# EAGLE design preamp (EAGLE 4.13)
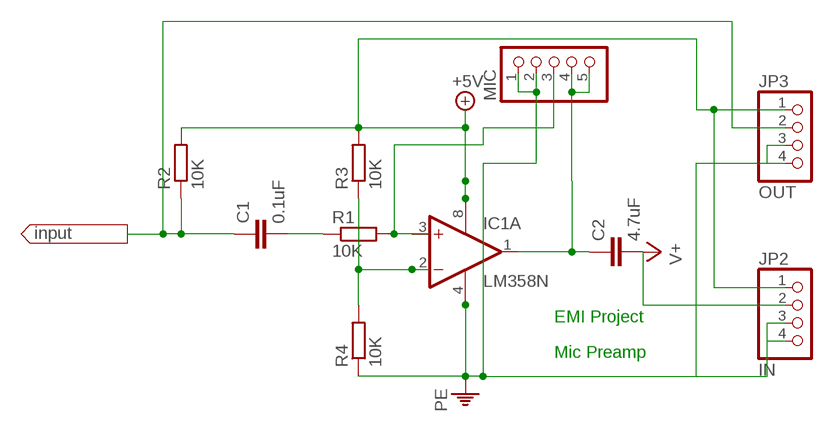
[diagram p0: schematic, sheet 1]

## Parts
C1  0.1uF  C-EU025-024X044  [C025-024X044]
C2  4.7uF  C-EU025-024X044  [C025-024X044]
IC1  LM358N  [DIL08]
JP2  IN  PINHD-1X4  [1X04]
JP3  OUT  PINHD-1X4  [1X04]
MIC  PINHD-1X5  [1X05]
R1  10K  R-EU_0207/7  [0207/7]
R2  10K  R-EU_0207/7  [0207/7]
R3  10K  R-EU_0207/7  [0207/7]
R4  10K  R-EU_0207/7  [0207/7]

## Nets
+9V: IC1.8(P:V+) JP2.1 JP3.1 R2.2 R3.2 ; supply symbol labelled +5V
N$1: C1.2 R1.1
N$2: C2.1 IC1.1(A:OUT) MIC.4 MIC.5
N$3: C1.1 JP3.2 R2.1
N$6: IC1.2(A:-IN) R3.1 R4.2
N$7: MIC.3 R1.2
PE: IC1.4(P:V-) JP2.3 JP2.4 JP3.3 JP3.4 MIC.1 MIC.2 R4.1
V+: C2.2 JP2.2
Unconnected: IC1.3(A:+IN) IC1.5(B:+IN) IC1.6(B:-IN) IC1.7(B:OUT)

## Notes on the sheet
- EMI Project
- Mic Preamp

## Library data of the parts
C1 C2 = rcl:C-EU: CAPACITOR, European symbol
IC1 = linear:LM358: OP AMP also LM158; LM258; LM2904 Source: http://cache.national.com/ds/LM/LM158.pdf
JP2 JP3 = pinhead:PINHD-1X4: PIN HEADER
MIC = pinhead:PINHD-1X5: PIN HEADER
R1-R4 = rcl:R-EU_: RESISTOR, European symbol

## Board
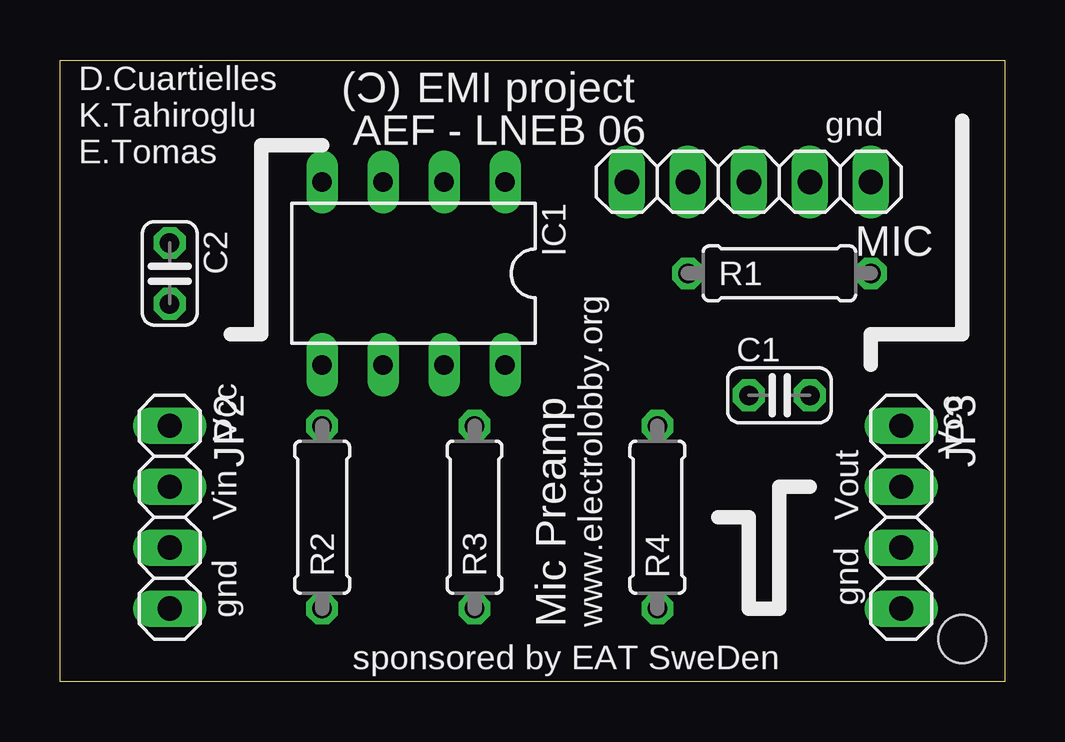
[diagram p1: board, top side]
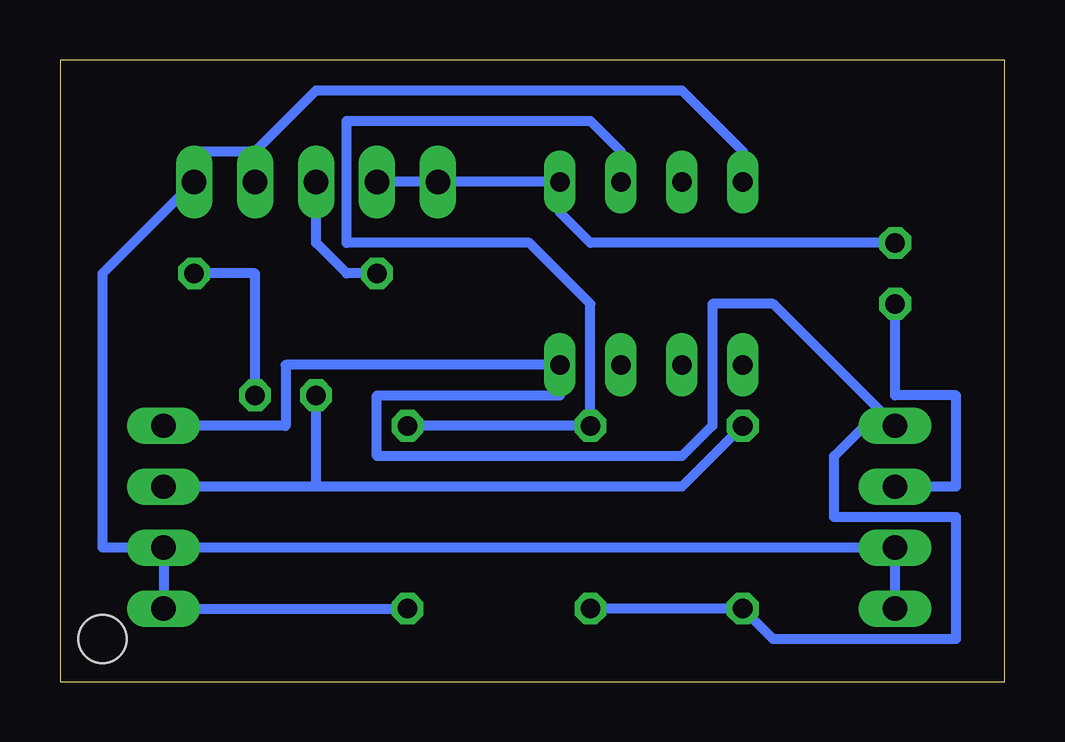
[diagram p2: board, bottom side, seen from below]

Size 39.37 x 25.91 mm. Coordinates in mm from the lower left corner, seen from the top.
Outline: 0,0 0,25.91 39.37,25.91 39.37,0 0,0
Copper layers (1*16): Top 0.035mm / dielectric 1.5mm / Bottom 0.035mm
Design rules "default": minimum track width 10mil, minimum drill 24mil, track to track 8mil, track to pad 8mil, pad to pad 8mil, via to via 8mil, smd to smd 8mil, copper to edge 40mil, drill to drill 8mil, minimum pad ring 10mil, minimum via ring 8mil, stop-mask expansion 4mil, vias tented up to drill 0mil, thermal gap 10mil
Holes 2 mm at 37.59,1.78

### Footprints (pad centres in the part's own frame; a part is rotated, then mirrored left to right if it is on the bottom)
C025-024X044 = drill 0.813 octagon: 1 -1.27,0; 2 1.27,0
DIL08 = drill 0.813 long: 1 -3.81,-3.81; 2 -1.27,-3.81; 3 1.27,-3.81; 4 3.81,-3.81; 5 3.81,3.81; 6 1.27,3.81; 7 -1.27,3.81; 8 -3.81,3.81
1X04 = drill 1.016 long: 1 -3.81,0; 2 -1.27,0; 3 1.27,0; 4 3.81,0
1X05 = drill 1.016 long: 1 -5.08,0; 2 -2.54,0; 3 0,0; 4 2.54,0; 5 5.08,0
0207/7 = drill 0.813 octagon: 1 -3.81,0; 2 3.81,0

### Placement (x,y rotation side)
C1  29.97,11.94 0 top
C2  4.57,17.02 270 top
IC1  14.73,17.02 180 top
JP2  4.57,6.86 270 top
JP3  35.05,6.86 270 top
MIC  28.7,20.83 180 top
R1  29.97,17.02 180 top
R2  10.92,6.86 270 top
R3  17.27,6.86 270 top
R4  24.89,6.86 90 top

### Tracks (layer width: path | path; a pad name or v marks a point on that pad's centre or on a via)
+9V
  Bottom 0.406: JP3.1 29.97,10.67 29.97,13.21 IC1.8 18.54,11.94 26.16,11.94 26.16,9.4 13.46,9.4 12.19,10.67 12.19,15.75 9.65,15.75 JP2.1 5.84,10.67 7.11,9.4 7.11,6.86 2.03,6.86 2.03,1.78 9.65,1.78 R2.2 R3.2
N$1
  Bottom 0.406: C1.2 31.24,17.02 R1.1
N$2
  Bottom 0.406: MIC.4 MIC.5 IC1.1 18.54,19.56 17.27,18.29 C2.1
N$3
  Bottom 0.406: R2.1 13.46,8.13 28.7,8.13 | 28.7,8.13 JP3.2 | 28.7,8.13 C1.1
N$6
  Bottom 0.406: R4.2 R3.1 17.27,15.75 19.81,18.29 27.43,18.29 27.43,23.37 17.27,23.37 16,22.1 IC1.2
N$7
  Bottom 0.406: R1.2 27.43,17.02 28.7,18.29 MIC.3
PE
  Bottom 0.406: 31.24,22.1 28.7,24.64 13.46,24.64 10.92,22.1 IC1.4 | 31.24,22.1 33.78,22.1 MIC.1 37.59,17.02 37.59,5.59 JP3.3 | 31.24,22.1 MIC.2 | JP2.4 JP2.3 JP3.3 | R4.1 JP3.4 JP3.3
V+
  Bottom 0.406: C2.2 4.57,11.94 2.03,11.94 2.03,8.13 JP2.2

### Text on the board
tPlace: D.Cuartielles | EMI project | K.Tahiroglu | AEF - LNEB 06 | gnd | E.Tomas | Vcc | Vcc | Vin | Vout | gnd | gnd | Mic Preamp | www.electrolobby.org | sponsored by EAT SweDen
tNames: (C)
